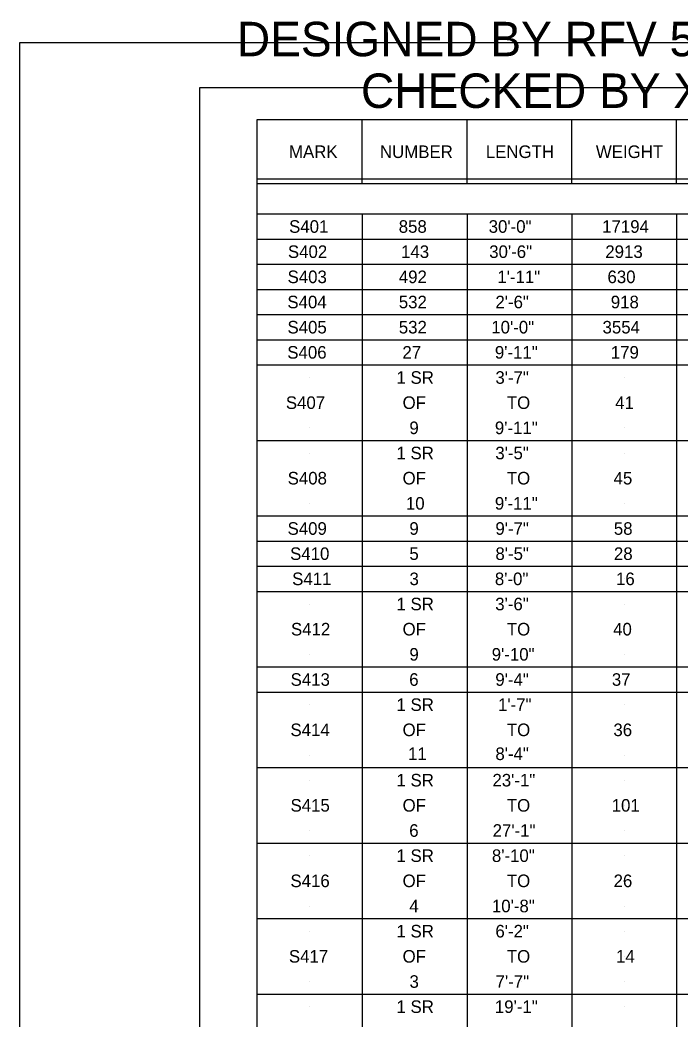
# Model space of a CAD drawing. Extents: x -31.1 to 2.9, y 8.5 to 31.4.
# Drawn here: x -31.13 to -23.78, y 19.62 to 30.73 of the extents above; entities that cross this region are included whole.
import ezdxf

# ---------------------------------------------------------------- set-up
doc = ezdxf.new("R2010")
doc.units = 0
for name, color, linetype in [('BR_P_Gen_Text', 7, 'Continuous'), ('Default', 7, 'Continuous'), ('SC_Scratch1', 7, 'Continuous'), ('SC_Scratch2', 7, 'Continuous')]:
    doc.layers.add(name, color=color, linetype=linetype)

msp = doc.modelspace()

# ---------------------------------------------------------------- linework, layer by layer
at = {"layer": 'BR_P_Gen_Text'}
for p, q in [((-28.487, 29.627), (-16.32, 29.627)), ((-27.32, 28.91), (-27.32, 29.627)), ((-26.153, 28.91), (-26.153, 29.627)), ((-24.987, 28.91), (-24.987, 29.627)), ((-23.82, 28.91), (-23.82, 29.627)), ((-16.32, 28.962), (-28.487, 28.962)), ((-17.665, 28.91), (-28.487, 28.91)), ((-16.32, 28.91), (-28.487, 28.91)), ((-28.487, 28.577), (-16.32, 28.577)), ((-27.32, 28.577), (-27.32, 14.017)), ((-26.153, 28.577), (-26.153, 14.017)), ((-24.987, 28.577), (-24.987, 13.737)), ((-23.82, 28.577), (-23.82, 13.737)), ((-28.487, 28.297), (-16.32, 28.297)), ((-28.487, 28.017), (-16.32, 28.017)), ((-28.487, 27.737), (-16.32, 27.737)), ((-28.487, 27.457), (-16.32, 27.457)), ((-28.487, 27.177), (-16.32, 27.177)), ((-28.487, 26.897), (-16.32, 26.897)), ((-28.487, 26.057), (-16.32, 26.057)), ((-28.487, 25.217), (-16.32, 25.217)), ((-28.487, 24.937), (-16.32, 24.937)), ((-28.487, 24.657), (-16.32, 24.657)), ((-28.487, 24.377), (-16.32, 24.377)), ((-28.487, 23.537), (-16.32, 23.537)), ((-28.487, 23.257), (-16.32, 23.257)), ((-28.487, 22.417), (-16.32, 22.417)), ((-28.487, 21.577), (-16.32, 21.577)), ((-28.487, 20.737), (-16.32, 20.737)), ((-28.487, 19.897), (-16.32, 19.897))]:
    msp.add_line(p, q, dxfattribs=at)
for points in [[(-31.128, 30.484), (2.872, 30.484), (2.872, 8.484), (-31.128, 8.484)], [(-29.128, 29.984), (1.372, 29.984), (1.372, 8.984), (-29.128, 8.984)]]:
    msp.add_lwpolyline(points, close=True, dxfattribs=at)
at = {"layer": 'Default'}
msp.add_line((-28.487, 13.737), (-28.487, 29.627), dxfattribs=at)
at = {"layer": 'SC_Scratch1'}
for p, q in [((-27.903, 28.437), (-27.903, 28.437)), ((-26.737, 28.437), (-26.737, 28.437)), ((-25.549, 28.437), (-25.549, 28.437)), ((-24.403, 28.437), (-24.403, 28.437)), ((-27.903, 28.157), (-27.903, 28.157)), ((-26.737, 28.157), (-26.737, 28.157)), ((-25.549, 28.157), (-25.549, 28.157)), ((-24.403, 28.157), (-24.403, 28.157)), ((-27.903, 27.877), (-27.903, 27.877)), ((-26.737, 27.877), (-26.737, 27.877)), ((-25.549, 27.877), (-25.549, 27.877)), ((-24.403, 27.877), (-24.403, 27.877)), ((-27.903, 27.597), (-27.903, 27.597)), ((-26.737, 27.597), (-26.737, 27.597)), ((-25.549, 27.597), (-25.549, 27.597)), ((-24.403, 27.597), (-24.403, 27.597)), ((-27.903, 27.317), (-27.903, 27.317)), ((-26.737, 27.317), (-26.737, 27.317)), ((-25.549, 27.317), (-25.549, 27.317)), ((-24.403, 27.317), (-24.403, 27.317)), ((-27.903, 27.037), (-27.903, 27.037)), ((-26.737, 27.037), (-26.737, 27.037)), ((-25.549, 27.037), (-25.549, 27.037)), ((-24.403, 27.037), (-24.403, 27.037)), ((-27.903, 26.757), (-27.903, 26.757)), ((-26.737, 26.757), (-26.737, 26.757)), ((-25.549, 26.757), (-25.549, 26.757)), ((-24.403, 26.757), (-24.403, 26.757)), ((-27.903, 26.477), (-27.903, 26.477)), ((-26.737, 26.477), (-26.737, 26.477)), ((-25.549, 26.477), (-25.549, 26.477)), ((-24.403, 26.477), (-24.403, 26.477)), ((-27.903, 26.197), (-27.903, 26.197)), ((-26.737, 26.197), (-26.737, 26.197)), ((-25.549, 26.197), (-25.549, 26.197)), ((-24.403, 26.197), (-24.403, 26.197)), ((-27.903, 25.917), (-27.903, 25.917)), ((-26.737, 25.917), (-26.737, 25.917)), ((-25.549, 25.917), (-25.549, 25.917)), ((-24.403, 25.917), (-24.403, 25.917)), ((-27.903, 25.637), (-27.903, 25.637)), ((-26.737, 25.637), (-26.737, 25.637)), ((-25.549, 25.637), (-25.549, 25.637)), ((-24.403, 25.637), (-24.403, 25.637)), ((-27.903, 25.357), (-27.903, 25.357)), ((-26.737, 25.357), (-26.737, 25.357)), ((-25.549, 25.357), (-25.549, 25.357)), ((-24.403, 25.357), (-24.403, 25.357)), ((-27.903, 25.077), (-27.903, 25.077)), ((-26.737, 25.077), (-26.737, 25.077)), ((-25.549, 25.077), (-25.549, 25.077)), ((-24.403, 25.077), (-24.403, 25.077)), ((-27.903, 24.797), (-27.903, 24.797)), ((-26.737, 24.797), (-26.737, 24.797)), ((-25.549, 24.797), (-25.549, 24.797)), ((-24.403, 24.797), (-24.403, 24.797)), ((-27.903, 24.517), (-27.903, 24.517)), ((-26.737, 24.517), (-26.737, 24.517)), ((-25.549, 24.517), (-25.549, 24.517)), ((-24.403, 24.517), (-24.403, 24.517)), ((-27.903, 24.237), (-27.903, 24.237)), ((-26.737, 24.237), (-26.737, 24.237)), ((-25.549, 24.237), (-25.549, 24.237)), ((-24.403, 24.237), (-24.403, 24.237)), ((-27.903, 23.957), (-27.903, 23.957)), ((-26.737, 23.957), (-26.737, 23.957)), ((-25.549, 23.957), (-25.549, 23.957)), ((-24.403, 23.957), (-24.403, 23.957)), ((-27.903, 23.677), (-27.903, 23.677)), ((-26.737, 23.677), (-26.737, 23.677)), ((-25.549, 23.677), (-25.549, 23.677)), ((-24.403, 23.677), (-24.403, 23.677)), ((-27.903, 23.397), (-27.903, 23.397)), ((-26.737, 23.397), (-26.737, 23.397)), ((-25.549, 23.397), (-25.549, 23.397)), ((-24.403, 23.397), (-24.403, 23.397)), ((-27.903, 23.117), (-27.903, 23.117)), ((-26.737, 23.117), (-26.737, 23.117)), ((-25.549, 23.117), (-25.549, 23.117)), ((-24.403, 23.117), (-24.403, 23.117)), ((-27.903, 22.837), (-27.903, 22.837)), ((-26.737, 22.837), (-26.737, 22.837)), ((-25.549, 22.837), (-25.549, 22.837)), ((-24.403, 22.837), (-24.403, 22.837)), ((-27.903, 22.557), (-27.903, 22.557)), ((-26.737, 22.557), (-26.737, 22.557)), ((-25.549, 22.557), (-25.549, 22.557)), ((-24.403, 22.557), (-24.403, 22.557)), ((-27.903, 22.277), (-27.903, 22.277)), ((-26.737, 22.277), (-26.737, 22.277)), ((-25.549, 22.277), (-25.549, 22.277)), ((-24.403, 22.277), (-24.403, 22.277)), ((-27.903, 21.997), (-27.903, 21.997)), ((-26.737, 21.997), (-26.737, 21.997)), ((-25.549, 21.997), (-25.549, 21.997)), ((-24.403, 21.997), (-24.403, 21.997)), ((-27.903, 21.717), (-27.903, 21.717)), ((-26.737, 21.717), (-26.737, 21.717)), ((-25.549, 21.717), (-25.549, 21.717)), ((-24.403, 21.717), (-24.403, 21.717)), ((-27.903, 21.437), (-27.903, 21.437)), ((-26.737, 21.437), (-26.737, 21.437)), ((-25.549, 21.437), (-25.549, 21.437)), ((-24.403, 21.437), (-24.403, 21.437)), ((-27.903, 21.157), (-27.903, 21.157)), ((-26.737, 21.157), (-26.737, 21.157)), ((-25.549, 21.157), (-25.549, 21.157)), ((-24.403, 21.157), (-24.403, 21.157)), ((-27.903, 20.877), (-27.903, 20.877)), ((-26.737, 20.877), (-26.737, 20.877)), ((-25.549, 20.877), (-25.549, 20.877)), ((-24.403, 20.877), (-24.403, 20.877)), ((-27.903, 20.597), (-27.903, 20.597)), ((-26.737, 20.597), (-26.737, 20.597)), ((-25.549, 20.597), (-25.549, 20.597)), ((-24.403, 20.597), (-24.403, 20.597)), ((-27.903, 20.317), (-27.903, 20.317)), ((-26.737, 20.317), (-26.737, 20.317)), ((-25.549, 20.317), (-25.549, 20.317)), ((-24.403, 20.317), (-24.403, 20.317)), ((-27.903, 20.037), (-27.903, 20.037)), ((-26.737, 20.037), (-26.737, 20.037)), ((-25.549, 20.037), (-25.549, 20.037)), ((-24.403, 20.037), (-24.403, 20.037)), ((-27.903, 19.757), (-27.903, 19.757)), ((-26.737, 19.757), (-26.737, 19.757)), ((-25.549, 19.757), (-25.549, 19.757)), ((-24.403, 19.757), (-24.403, 19.757))]:
    msp.add_line(p, q, dxfattribs=at)

# ---------------------------------------------------------------- texts
at = {"layer": 'BR_P_Gen_Text'}
for s, p in [('S401', (-28.133, 28.367)), ('858', (-26.913, 28.367)), ('30\'-0"', (-25.912, 28.367)), ('17194', (-24.649, 28.367)), ('S402', (-28.146, 28.087)), ('143', (-26.887, 28.087)), ('30\'-6"', (-25.906, 28.087)), ('2913', (-24.614, 28.087)), ('S403', (-28.15, 27.807)), ('492', (-26.912, 27.807)), ('1\'-11"', (-25.815, 27.807)), ('630', (-24.59, 27.807)), ('S404', (-28.152, 27.527)), ('532', (-26.912, 27.527)), ('2\'-6"', (-25.837, 27.527)), ('918', (-24.553, 27.527)), ('S405', (-28.151, 27.247)), ('532', (-26.912, 27.247)), ('10\'-0"', (-25.883, 27.247)), ('3554', (-24.645, 27.247)), ('S406', (-28.153, 26.967)), ('27', (-26.872, 26.967)), ('9\'-11"', (-25.843, 26.967)), ('179', (-24.553, 26.967)), ('1 SR', (-26.938, 26.687)), ('1 SR', (-26.938, 26.687)), ('3\'-7"', (-25.837, 26.687)), ('S407', (-28.169, 26.407)), ('OF', (-26.87, 26.407)), ('OF', (-26.87, 26.407)), ('TO', (-25.71, 26.407)), ('41', (-24.504, 26.407)), ('9', (-26.794, 26.127)), ('9', (-26.794, 26.127)), ('9\'-11"', (-25.843, 26.127)), ('1 SR', (-26.938, 25.847)), ('3\'-5"', (-25.838, 25.847)), ('S408', (-28.149, 25.567)), ('OF', (-26.87, 25.567)), ('TO', (-25.71, 25.567)), ('45', (-24.522, 25.567)), ('10', (-26.833, 25.287)), ('9\'-11"', (-25.843, 25.287)), ('S409', (-28.15, 25.007)), ('9', (-26.794, 25.007)), ('9\'-7"', (-25.837, 25.007)), ('58', (-24.519, 25.007)), ('S410', (-28.122, 24.727)), ('5', (-26.794, 24.727)), ('8\'-5"', (-25.837, 24.727)), ('28', (-24.518, 24.727)), ('S411', (-28.099, 24.447)), ('3', (-26.793, 24.447)), ('8\'-0"', (-25.843, 24.447)), ('16', (-24.495, 24.447)), ('1 SR', (-26.938, 24.167)), ('3\'-6"', (-25.839, 24.167)), ('S412', (-28.112, 23.887)), ('OF', (-26.87, 23.887)), ('TO', (-25.71, 23.887)), ('40', (-24.527, 23.887)), ('9', (-26.794, 23.607)), ('9\'-10"', (-25.878, 23.607)), ('S413', (-28.116, 23.327)), ('6', (-26.796, 23.327)), ('9\'-4"', (-25.838, 23.327)), ('37', (-24.541, 23.327)), ('1 SR', (-26.938, 23.047)), ('1\'-7"', (-25.808, 23.047)), ('S414', (-28.118, 22.767)), ('OF', (-26.87, 22.767)), ('TO', (-25.71, 22.767)), ('36', (-24.524, 22.767)), ('11', (-26.81, 22.501)), ('8\'-4"', (-25.837, 22.501)), ('1 SR', (-26.938, 22.207)), ('23\'-1"', (-25.87, 22.207)), ('S415', (-28.117, 21.927)), ('OF', (-26.87, 21.927)), ('TO', (-25.71, 21.927)), ('101', (-24.543, 21.927)), ('6', (-26.796, 21.647)), ('27\'-1"', (-25.868, 21.647)), ('1 SR', (-26.938, 21.367)), ('8\'-10"', (-25.876, 21.367)), ('S416', (-28.118, 21.087)), ('OF', (-26.87, 21.087)), ('TO', (-25.71, 21.087)), ('26', (-24.522, 21.087)), ('4', (-26.795, 20.807)), ('10\'-8"', (-25.876, 20.807)), ('1 SR', (-26.938, 20.527)), ('6\'-2"', (-25.837, 20.527)), ('S417', (-28.135, 20.247)), ('OF', (-26.87, 20.247)), ('TO', (-25.71, 20.247)), ('14', (-24.495, 20.247)), ('3', (-26.793, 19.967)), ('7\'-7"', (-25.835, 19.967)), ('1 SR', (-26.938, 19.687)), ('19\'-1"', (-25.843, 19.687))]:
    msp.add_text(s, height=0.14, dxfattribs=at).set_placement(p)
at = {"layer": 'Default'}
for s, p in [('MARK', (-28.134, 29.199)), ('NUMBER', (-27.122, 29.199)), ('LENGTH', (-25.944, 29.199)), ('WEIGHT', (-24.719, 29.199))]:
    msp.add_text(s, height=0.14, dxfattribs=at).set_placement(p)
at = {"layer": 'SC_Scratch2'}
for s, p in [('DESIGNED BY RFV 5/15/20', (-28.714, 30.331)), ('CHECKED BY XXX', (-27.333, 29.756))]:
    msp.add_text(s, height=0.38343, dxfattribs=at).set_placement(p)

doc.saveas('drawing.dxf')
